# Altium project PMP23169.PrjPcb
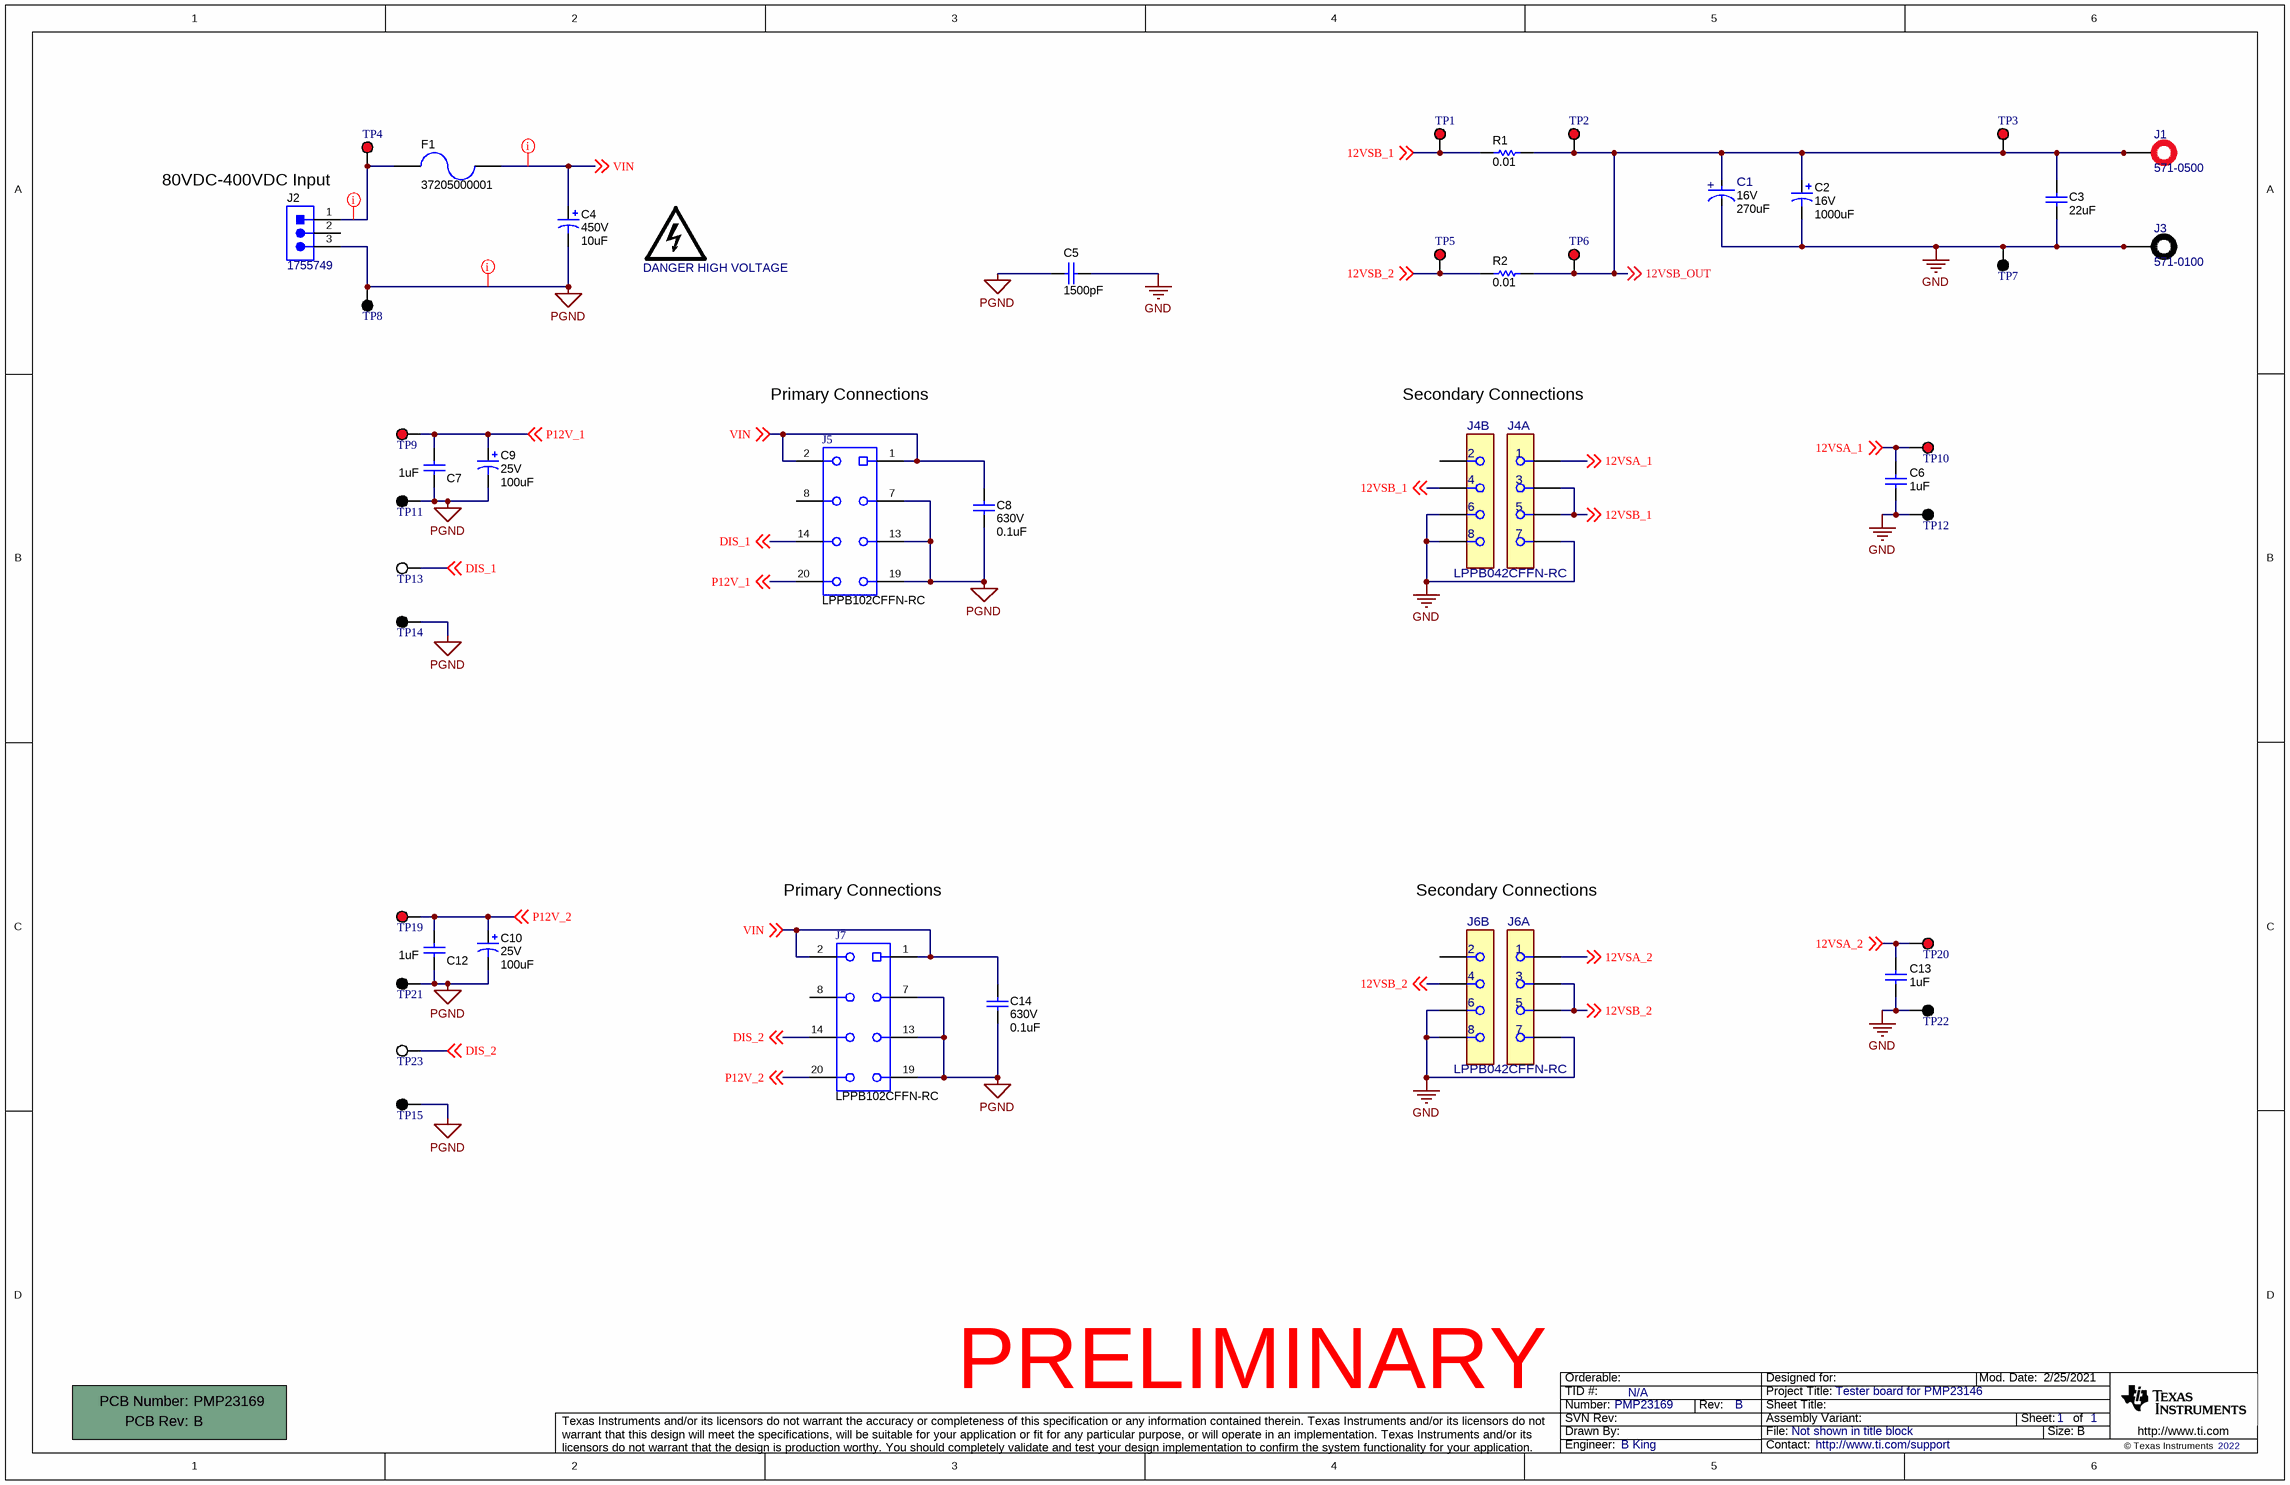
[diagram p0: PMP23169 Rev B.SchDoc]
TID: N/A; TechSupport: http://www.ti.com/support; SCH_Rev: B; PRJ_Title: Tester board for PMP23146; PRJ_Number: PMP23169; PRJ_Engineer: B King; PCB_Rev: B; PCB_Layout: B King; CopyrightYear: 2022
1 sheet, 45 parts. Net scope: global (net labels, ports and power ports of the same name join across sheets).
Board file: PMP23169 Rev B.PcbDoc

## Sheet PMP23169 Rev B.SchDoc
size 431 x 279 mm; Date: Not shown in title block; ApprovedBy: Not shown in title block; CheckedBy: Not shown in title block; Author: Not shown in title block; CompanyName: Not shown in title block; Engineer: Not shown in title block; Organization: Not shown in title block; Address1: Not shown in title block; Address2: Not shown in title block; Address3: Not shown in title block; Address4: Not shown in title block; DocumentNumber: 2; Revision: Use project parameter SCH_Rev; SheetNumber: 1; SheetTotal: 1; PageSetup: Record=PageOptions¦CenterHorizontal=True¦CenterVertical=True¦PrintScale=1.00¦XCorrection=1.00¦YCorrection=1.00¦PrintKind=0¦BorderSize=5000000¦LeftOffset=0¦BottomOffset=0¦Orientation=2¦PaperLength=1000¦PaperWidth=1000¦Scale=100¦PaperSource=15¦PrintQuality=600¦MediaType=1¦DitherType=10¦PaperKind=Letter¦PrintScaleMode=1

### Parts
!PCB1  Printed Circuit Board  (value not drawn)  (mechanical)
C1  VDC_V: 16V  ValueDisplayed: 270uF  [FP-APSG160ELL271MF08J_RADIAL-MFG]  (hidden comment: APSG160ELL271MF08J)
C2  VDC_V: 16V  ValueDisplayed: 1000uF  [Chemi-Con_1000x2000]  (hidden comment: EKZE160ELL102MJ20S)
C3  ValueDisplayed: 22uF  [1206_180L]  (hidden comment: C3216X5R1V226M160AC)
C4  VDC_V: 450V  ValueDisplayed: 10uF  [EE_1000x2000]  (hidden comment: EEUEE2W100U)
C5  ValueDisplayed: 1500pF  [DK1_86]  (hidden comment: DK1E3EA152M86RAH01)
C6  ValueDisplayed: 1uF  [0603S]  (hidden comment: C1608X7R1E105K080AB)
C7  ValueDisplayed: 1uF  [0603S]  (hidden comment: C1608X7R1E105K080AB)
C8  VDC_V: 630V  ValueDisplayed: 0.1uF  [1808_215_L]  (hidden comment: C1808W104KBRACTU)
C9  VDC_V: 25V  ValueDisplayed: 100uF  [BT_800x1150]  (hidden comment: UBT1E101MPD1TD)
C10  VDC_V: 25V  ValueDisplayed: 100uF  [BT_800x1150]  (hidden comment: UBT1E101MPD1TD)
C12  ValueDisplayed: 1uF  [0603S]  (hidden comment: C1608X7R1E105K080AB)
C13  ValueDisplayed: 1uF  [0603S]  (hidden comment: C1608X7R1E105K080AB)
C14  VDC_V: 630V  ValueDisplayed: 0.1uF  [1808_215_L]  (hidden comment: C1808W104KBRACTU)
F1  37205000001  [FUSE_372]
J1  571-0500  [571-0500]
J2  1755749  [CONN_1755749]
J3  571-0100  [571-0100]
J4  LPPB042CFFN-RC  [FP-LPPB042CFFN-RC_HDR8-MFG]  (parts A,B of 2)
J5  LPPB102CFFN-RC  [Sullins_LPPB102CFFN]
J6  LPPB042CFFN-RC  [FP-LPPB042CFFN-RC_HDR8-MFG]  (parts A,B of 2)
J7  LPPB102CFFN-RC  [Sullins_LPPB102CFFN]
LOGO1  DANGER HIGH VOLTAGE  [IEC_HighVoltage_Medium]  (no BOM)
R1  ValueDisplayed: 0.01  [2512]  (hidden comment: WSL2512R0100FEA)
R2  ValueDisplayed: 0.01  [2512]  (hidden comment: WSL2512R0100FEA)
TP1  5010  [Keystone5010]  (value not drawn)
TP2  5010  [Keystone5010]  (value not drawn)
TP3  5010  [Keystone5010]  (value not drawn)
TP4  5010  [Keystone5010]  (value not drawn)
TP5  5010  [Keystone5010]  (value not drawn)
TP6  5010  [Keystone5010]  (value not drawn)
TP7  5011  [Keystone5011]  (value not drawn)
TP8  5011  [Keystone5011]  (value not drawn)
TP9  5010  [Keystone5010]  (value not drawn)
TP10  5010  [Keystone5010]  (value not drawn)
TP11  5011  [Keystone5011]  (value not drawn)
TP12  5011  [Keystone5011]  (value not drawn)
TP13  5012  [Keystone5012]  (value not drawn)
TP14  5011  [Keystone5011]  (value not drawn)
TP15  5011  [Keystone5011]  (value not drawn)
TP19  5010  [Keystone5010]  (value not drawn)
TP20  5010  [Keystone5010]  (value not drawn)
TP21  5011  [Keystone5011]  (value not drawn)
TP22  5011  [Keystone5011]  (value not drawn)
TP23  5012  [Keystone5012]  (value not drawn)

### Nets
GND: C1.1(CATHODE) C2.2(-) C3.2 C5.1 C6.1 C13.1 J3.1 J3.2 J4.6 J4.7 J4.8 J6.6 J6.7 J6.8 TP7.1 TP12.1 TP22.1
PGND: C4.2(-) C5.2 C7.1 C8.2 C9.2(-) C10.2(-) C12.1 C14.2 J2.3 J5.7 J5.13 J5.19 J7.7 J7.13 J7.19 TP8.1 TP11.1 TP14.1 TP15.1 TP21.1
12VSA_1: C6.2 J4.1 TP10.1 ; off-sheet 12VSA_1
12VSA_2: C13.2 J6.1 TP20.1 ; off-sheet 12VSA_2
12VSB_1: J4.3 J4.4 J4.5 R1.1 TP1.1 ; off-sheet 12VSB_1
12VSB_2: J6.3 J6.4 J6.5 R2.1 TP5.1 ; off-sheet 12VSB_2
12VSB_OUT: C1.2(ANODE) C2.1(+) C3.1 J1.1 J1.2 R1.2 R2.2 TP2.1 TP3.1 TP6.1 ; off-sheet 12VSB_OUT
DIS_1: J5.14 TP13.1 ; off-sheet DIS_1
DIS_2: J7.14 TP23.1 ; off-sheet DIS_2
P12V_1: C7.2 C9.1(+) J5.20 TP9.1 ; off-sheet P12V_1
P12V_2: C10.1(+) C12.2 J7.20 TP19.1 ; off-sheet P12V_2
VIN: C4.1(+) C8.1 C14.1 F1.1 J5.1 J5.2 J7.1 J7.2 ; off-sheet VIN
NetF1_2: F1.2 J2.1 TP4.1

Not connected (* = marked no-connect by the designer): J2 2; J4 2; J5 8; J6 2; J7 8

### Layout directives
net class 400V: NetF1_2, VIN
net class Primary LV: PGND

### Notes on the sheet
- 80VDC-400VDC Input
- Primary Connections
- Secondary Connections
- PRELIMINARY

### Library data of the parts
!PCB1 = CMP-0003618-2: Manufacturer: Any; PartNumber: PMP23169
C1 = CMP-0091874-1: 270µF 16V Aluminum - Polymer Capacitors Radial, Can 10mOhm 20000 Hrs @ 105°C; Manufacturer: Nippon Chemi-Con; IRMS_A: 5.08A; AEC Qualified: No; Esr: 0.01; Tolerance_%: 20%; SizeZ_mm: 9.2mm; Dissipation Factor: 12%; Life: 20000Hours; Leakage Current: 864uA
C2 = CMP-0010386-1: CAP, AL, 1000 uF, 16 V, +/- 20%, TH; Manufacturer: Chemi-Con; TaMin_C: -40°C; Polarized: Y; SizeAreaWB_mm2: 144; Value1: Unknown; U/M: EA; Value: 1000uF; TaMax_C: 105°C; SizeZ_mm: 21.5; SizeX_mm: 10; Cap_Case: 10x20; SizeArea_mm2: 100; CompType: Capacitor; AEC Qualified: N; Cap_F: 1mF; IRMS_A: 1.82A; AEC Category: Q200
C3 = CMP-0008667-2: CAP, CERM, 22 uF, 35 V, +/- 20%, X5R, 1206; Manufacturer: TDK; TaMin_C: -55°C; ESR_ohm: 2.398m; Polarized: N; SizeAreaWB_mm2: 10.92; Value1: 0.002398 ohm; U/M: EA; Value: 22uF; TaMax_C: 85°C; SizeZ_mm: 1.8; SizeX_mm: 3.2; SizeY_mm: 1.6; Cap_Case: 1206_180; Value2: 35V; SizeArea_mm2: 5.12; Cap_F: 22µF; IRMS_A: 4.68507A; AEC Category: Q200
C4 = CMP-0010028-3: CAP, AL, 10 uF, 450 V, +/- 20%, TH; Manufacturer: Panasonic; TaMin_C: -25°C; Polarized: Y; SizeAreaWB_mm2: 144; Value1: Unknown; U/M: EA; Value: 10uF; TaMax_C: 105°C; SizeZ_mm: 22; SizeX_mm: 10; Cap_Case: 10x20mm; SizeArea_mm2: 100; CompType: Capacitor; AEC Qualified: N; Cap_F: 10µF; IRMS_A: 330mA; AEC Category: Q200
C5 = CMP-0077998-1: CAP, CERM, 1500 pF, X1 440 VAC/Y1 250 VAC, +/- 20%, E, 8x6mm; Manufacturer: MuRata; Cap_F: 1.5nF; SizeAreaWB_mm2: 107.2; VAC_X: 440; VAC_Y: 250; SizeArea_mm2: 68.4; AEC Qualified: N; AEC Category: Q200; Value: 1500pF; TaMax_C: 125°C; SizeZ_mm: 2.5; TaMin_C: -40°C; SizeY_mm: 6; U/M: EA; AC_Safety: X1Y1; CompType: Capacitor; SizeX_mm: 11.4
C6 C7 C12 C13 = CMP-0007040-4: CAP, CERM, 1 µF, 25 V, +/- 10%, X7R, 0603; Manufacturer: TDK; Polarized: N; CompType: Capacitor; Value: 1uF; U/M: EA; Cap_F: 1µF; Value1: Unknown; VDC_V: 25V; TaMin_C: -55°C; TaMax_C: 125°C; Cap_Case: 0603; AEC Category: Q200; SizeArea_mm2: 1.28; SizeAreaWB_mm2: 4.68; SizeX_mm: 1.6; SizeY_mm: 0.8; SizeZ_mm: 1
C8 C14 = CMP-0009318-2: CAP, CERM, 0.1 uF, 630 V, +/- 10%, X7R, 1808; Manufacturer: Kemet; TaMin_C: -55°C; Polarized: N; SizeAreaWB_mm2: 16.5; Value1: Unknown; U/M: EA; Value: 0.1uF; TaMax_C: 125°C; SizeZ_mm: 2.15; SizeX_mm: 4.5; SizeY_mm: 2; Cap_Case: 1808; SizeArea_mm2: 9; Cap_F: 100nF; AEC Category: Q200
C9 C10 = CMP-0010526-1: CAP, AL, 100 uF, 25 V, +/- 20%, 0.13 ohm, TH; Manufacturer: Nichicon; TaMin_C: -40°C; ESR_ohm: 0.13; Polarized: Y; SizeAreaWB_mm2: 100; U/M: EA; Value: 100uF; TaMax_C: 125°C; SizeZ_mm: 13.5; SizeX_mm: 8; Cap_Case: 8x11.5; SizeArea_mm2: 64; CompType: Capacitor; Cap_F: 100µF; IRMS_A: 500mA; AEC Category: Q200
F1 = CMP-0003549-2: Fuse, 0.5 A, 250VAC/VDC, TH; Manufacturer: Littelfuse; Irating_A: 500mA; VAC_V: 250V
J1 = CMP-0055393-3: Standard Banana Jack, insulated, 10A, red; Manufacturer: DEM Manufacturing; Green_REACh: Incomplete; Green_Lifecycle: Not Set
J2 = CMP-0055478-1: Terminal Block, 3x1, 5.08 mm, TH; Manufacturer: Phoenix Contact; CT: TRUE; CNHeader: FALSE
J3 = CMP-0055389-3: Standard Banana Jack, insulated, 10A, black; Manufacturer: DEM Manufacturing; Green_REACh: Incomplete; Green_Lifecycle: Not Set
J4 J6 = CMP-0093817-1: Manufacturer: Sullins Connector Solutions; ContactFinish: Gold,Nickel; Is Female: yes; SizeZ_mm: 4.7mm; Conn Gender: Female; Row_Count: 2; Current_A: 1A; DUT-Pitch_mm: 1.27mm; AEC Qualified: No; Conn Orientation: Straight
J5 J7 = CMP-BK1: Receptacle, 1.27mm, 10x2, Gold, TH; Manufacturer: Sullins Connector Solutions; SymbolCreator: a0412235; Gender: Female; Current_A: 1A; Cert_UL: Y; Row_Count: 2; Pitch_mm: 1.27
LOGO1 = CMP-0074835-1: IEC 61010-1 High Voltage Warning; SymbolCreator: a0412235
R1 R2 = CMP-0015850-2: RES, 0.01, 1%, 1 W, 2512; Manufacturer: Vishay-Dale; Power_W: 1W; TempCo: 75 ppm/C; Value_Code: R010; U/M: EA; Value: 0.01; EIA_Code: E96; SizeX_mm: 6.3; SizeY_mm: 3.2; SizeZ_mm: 0.71; SizeArea_mm2: 20.16; AEC Category: Q200
TP1-TP6 TP9 TP10 TP19 TP20 = CMP-0055147-1: Test Point, Multipurpose, Red, TH; Manufacturer: Keystone; CNHeader: FALSE; Green_Lifecycle: Active; Green_REACh: Passed; ContactFinish: Silver; CT: TRUE
TP7 TP8 TP11 TP12 TP14 TP15 TP21 TP22 = CMP-0055148-1: Test Point, Multipurpose, Black, TH; Manufacturer: Keystone; CNHeader: FALSE; Green_Lifecycle: Active; Green_REACh: Passed; ContactFinish: Silver; CT: TRUE
TP13 TP23 = CMP-0055149-1: Test Point, Multipurpose, White, TH; Manufacturer: Keystone; CNHeader: FALSE; Green_Lifecycle: Active; Green_REACh: Passed; ContactFinish: Silver; CT: TRUE

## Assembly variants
001: not fitted FID1 FID2 FID3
